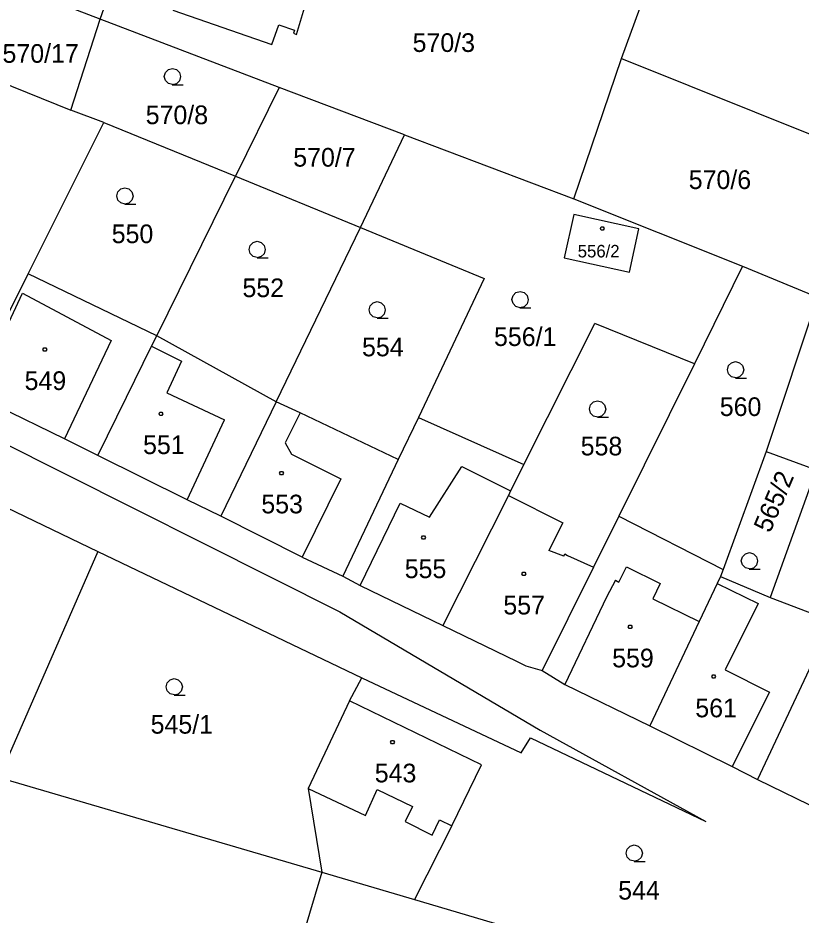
# Model space of a CAD drawing. Extents: x -759060 to -757386, y -1172273 to -1170948.
# Drawn here: x -758258.8 to -758187.4, y -1171734.6 to -1171652.9 of the extents above; entities that cross this region are included whole.
import ezdxf

# ---------------------------------------------------------------- set-up
doc = ezdxf.new("R2010")
doc.units = 0
for name, color, linetype in [('Vrstva 1', 7, 'Continuous'), ('Vrstva 12', 7, 'Continuous'), ('Vrstva 2', 7, 'Continuous'), ('Vrstva 3', 7, 'Continuous'), ('Vrstva 4', 7, 'Continuous'), ('Vrstva 5', 7, 'Continuous')]:
    doc.layers.add(name, color=color, linetype=linetype)

msp = doc.modelspace()

# ---------------------------------------------------------------- linework, layer by layer
at = {"layer": 'Vrstva 1'}
for p, q in [((-758251.29, -1171652.99), (-758245.38, -1171635.86)), ((-758251.29, -1171652.99), (-758258.76, -1171650.13)), ((-758233.41, -1171654.38), (-758232.51, -1171651.34)), ((-758203.79, -1171656.58), (-758202.08, -1171651.93)), ((-758244.67, -1171652.18), (-758235.65, -1171655.29)), ((-758253.97, -1171661.29), (-758251.29, -1171652.99)), ((-758234.98, -1171659.23), (-758251.29, -1171652.99)), ((-758235.65, -1171655.29), (-758235.03, -1171653.5)), ((-758235.03, -1171653.5), (-758233.59, -1171654)), ((-758233.59, -1171654), (-758233.69, -1171654.28)), ((-758233.69, -1171654.28), (-758233.41, -1171654.38)), ((-758208.12, -1171669.37), (-758203.79, -1171656.58)), ((-758203.79, -1171656.58), (-758181.48, -1171665.51)), ((-758261.39, -1171658.31), (-758253.97, -1171661.29)), ((-758234.98, -1171659.23), (-758238.98, -1171667.31)), ((-758223.55, -1171663.54), (-758234.98, -1171659.23)), ((-758250.97, -1171662.41), (-758253.97, -1171661.29)), ((-758257.87, -1171676.2), (-758250.97, -1171662.41)), ((-758250.97, -1171662.41), (-758238.98, -1171667.31)), ((-758227.57, -1171671.98), (-758223.55, -1171663.54)), ((-758223.55, -1171663.54), (-758208.12, -1171669.37)), ((-758246.15, -1171681.85), (-758238.98, -1171667.31)), ((-758238.98, -1171667.31), (-758227.57, -1171671.98)), ((-758208.12, -1171669.37), (-758192.74, -1171675.5)), ((-758208.13, -1171670.8), (-758209, -1171674.75)), ((-758202.2, -1171672.11), (-758208.13, -1171670.8)), ((-758235.27, -1171687.87), (-758227.57, -1171671.98)), ((-758227.57, -1171671.98), (-758216.29, -1171676.63)), ((-758203.06, -1171676.05), (-758202.2, -1171672.11)), ((-758209, -1171674.75), (-758203.06, -1171676.05)), ((-758192.74, -1171675.5), (-758197.13, -1171684.41)), ((-758192.74, -1171675.5), (-758185.93, -1171678.31)), ((-758263.26, -1171686.98), (-758257.87, -1171676.2)), ((-758246.15, -1171681.85), (-758257.87, -1171676.2)), ((-758216.29, -1171676.63), (-758222.3, -1171689.28)), ((-758286.85, -1171678.18), (-758229.45, -1171707)), ((-758185.93, -1171678.31), (-758190.6, -1171692.37)), ((-758212.68, -1171693.57), (-758206.2, -1171680.71)), ((-758197.13, -1171684.41), (-758206.2, -1171680.71)), ((-758246.61, -1171682.79), (-758246.15, -1171681.85)), ((-758235.27, -1171687.87), (-758246.15, -1171681.85)), ((-758248.89, -1171687.43), (-758246.61, -1171682.79)), ((-758197.13, -1171684.41), (-758204.03, -1171698.27)), ((-758254.55, -1171691.24), (-758262.74, -1171687.24)), ((-758251.51, -1171692.75), (-758248.89, -1171687.43)), ((-758235.27, -1171687.87), (-758240.3, -1171698.27)), ((-758233.07, -1171688.87), (-758235.27, -1171687.87)), ((-758277.01, -1171689.2), (-758251.53, -1171701.5)), ((-758224.13, -1171693.12), (-758233.07, -1171688.87)), ((-758222.3, -1171689.28), (-758224.13, -1171693.12)), ((-758222.3, -1171689.28), (-758212.68, -1171693.57)), ((-758251.51, -1171692.75), (-758254.55, -1171691.24)), ((-758243.36, -1171696.79), (-758251.51, -1171692.75)), ((-758190.6, -1171692.37), (-758194.52, -1171703.12)), ((-758190.6, -1171692.37), (-758186.03, -1171694.05)), ((-758224.13, -1171693.12), (-758229.17, -1171703.73)), ((-758212.68, -1171693.57), (-758213.89, -1171695.98)), ((-758186.03, -1171694.05), (-758190.23, -1171705.69)), ((-758213.89, -1171695.98), (-758214.09, -1171696.38)), ((-758240.3, -1171698.27), (-758243.36, -1171696.79)), ((-758214.09, -1171696.38), (-758215.64, -1171699.47)), ((-758214.09, -1171696.38), (-758209.13, -1171698.88)), ((-758232.9, -1171702.02), (-758240.3, -1171698.27)), ((-758204.03, -1171698.27), (-758206.33, -1171702.91)), ((-758204.03, -1171698.27), (-758194.52, -1171703.12)), ((-758215.64, -1171699.47), (-758220.06, -1171708.25)), ((-758209.13, -1171698.88), (-758210.41, -1171701.41)), ((-758251.53, -1171701.5), (-758260.55, -1171722.08)), ((-758251.53, -1171701.5), (-758227.44, -1171713.01)), ((-758209.04, -1171701.92), (-758210.41, -1171701.41)), ((-758209.04, -1171701.92), (-758208.94, -1171701.72)), ((-758208.94, -1171701.72), (-758208.69, -1171701.87)), ((-758208.69, -1171701.87), (-758206.33, -1171702.91)), ((-758232.9, -1171702.02), (-758229.17, -1171703.73)), ((-758206.33, -1171702.91), (-758211.02, -1171712.33)), ((-758194.52, -1171703.12), (-758194.76, -1171703.77)), ((-758229.17, -1171703.73), (-758227.6, -1171704.6)), ((-758194.76, -1171703.77), (-758195.06, -1171704.4)), ((-758194.76, -1171703.77), (-758190.23, -1171705.69)), ((-758227.6, -1171704.6), (-758220.06, -1171708.25)), ((-758195.06, -1171704.4), (-758196.69, -1171707.86)), ((-758190.23, -1171705.69), (-758184.62, -1171707.83)), ((-758229.45, -1171707), (-758211.2, -1171717.78)), ((-758220.06, -1171708.25), (-758213.35, -1171711.5)), ((-758196.69, -1171707.86), (-758201.21, -1171717.39)), ((-758184.62, -1171707.83), (-758191.39, -1171722.26)), ((-758213.35, -1171711.5), (-758212.49, -1171711.91)), ((-758212.49, -1171711.91), (-758211.02, -1171712.33)), ((-758211.02, -1171712.33), (-758208.95, -1171713.61)), ((-758228.58, -1171715.1), (-758227.44, -1171713.01)), ((-758227.44, -1171713.01), (-758212.94, -1171719.83)), ((-758208.95, -1171713.61), (-758201.21, -1171717.39)), ((-758228.58, -1171715.1), (-758232.34, -1171723.08)), ((-758216.55, -1171720.92), (-758228.58, -1171715.1)), ((-758201.21, -1171717.39), (-758193.7, -1171721.07)), ((-758211.2, -1171717.78), (-758196.08, -1171726.08)), ((-758212.94, -1171719.83), (-758212.08, -1171718.48)), ((-758212.08, -1171718.48), (-758196.08, -1171726.08)), ((-758219.25, -1171726.48), (-758216.55, -1171720.92)), ((-758193.7, -1171721.07), (-758191.39, -1171722.26)), ((-758260.55, -1171722.08), (-758231.11, -1171730.71)), ((-758191.39, -1171722.26), (-758181.67, -1171727.03)), ((-758232.34, -1171723.08), (-758231.11, -1171730.71)), ((-758196.08, -1171726.08), (-758196.08, -1171726.08)), ((-758219.25, -1171726.48), (-758222.66, -1171733.2)), ((-758231.11, -1171730.71), (-758236.26, -1171748.17)), ((-758231.11, -1171730.71), (-758222.66, -1171733.2)), ((-758222.66, -1171733.2), (-758206.53, -1171737.95))]:
    msp.add_line(p, q, dxfattribs=at)
at = {"layer": 'Vrstva 12'}
for p, q in [((-758233.41, -1171654.38), (-758232.51, -1171651.34)), ((-758244.67, -1171652.18), (-758235.65, -1171655.29)), ((-758235.65, -1171655.29), (-758235.03, -1171653.5)), ((-758235.03, -1171653.5), (-758233.59, -1171654)), ((-758233.59, -1171654), (-758233.69, -1171654.28)), ((-758233.69, -1171654.28), (-758233.41, -1171654.38)), ((-758208.13, -1171670.8), (-758209, -1171674.75)), ((-758202.2, -1171672.11), (-758208.13, -1171670.8)), ((-758203.06, -1171676.05), (-758202.2, -1171672.11)), ((-758209, -1171674.75), (-758203.06, -1171676.05)), ((-758262.74, -1171687.24), (-758258.39, -1171677.95)), ((-758258.39, -1171677.95), (-758250.29, -1171682.26)), ((-758250.29, -1171682.26), (-758254.55, -1171691.24)), ((-758248.89, -1171687.43), (-758246.61, -1171682.79)), ((-758246.61, -1171682.79), (-758243.88, -1171684.14)), ((-758243.88, -1171684.14), (-758245.23, -1171687.05)), ((-758245.23, -1171687.05), (-758239.97, -1171689.5)), ((-758254.55, -1171691.24), (-758262.74, -1171687.24)), ((-758251.51, -1171692.75), (-758248.89, -1171687.43)), ((-758235.27, -1171687.87), (-758240.3, -1171698.27)), ((-758233.07, -1171688.87), (-758235.27, -1171687.87)), ((-758243.36, -1171696.79), (-758239.97, -1171689.5)), ((-758233.07, -1171688.87), (-758234.43, -1171691.59)), ((-758234.43, -1171691.59), (-758233.87, -1171692.62)), ((-758243.36, -1171696.79), (-758251.51, -1171692.75)), ((-758233.87, -1171692.62), (-758229.38, -1171694.87)), ((-758221.27, -1171698.38), (-758218.35, -1171693.74)), ((-758218.35, -1171693.74), (-758213.89, -1171695.98)), ((-758229.38, -1171694.87), (-758232.9, -1171702.02)), ((-758213.89, -1171695.98), (-758214.09, -1171696.38)), ((-758214.09, -1171696.38), (-758215.64, -1171699.47)), ((-758214.09, -1171696.38), (-758215.64, -1171699.47)), ((-758214.09, -1171696.38), (-758209.13, -1171698.88)), ((-758227.6, -1171704.6), (-758223.96, -1171697.08)), ((-758223.96, -1171697.08), (-758221.27, -1171698.38)), ((-758232.9, -1171702.02), (-758240.3, -1171698.27)), ((-758215.64, -1171699.47), (-758220.06, -1171708.25)), ((-758215.64, -1171699.47), (-758220.06, -1171708.25)), ((-758209.13, -1171698.88), (-758210.41, -1171701.41)), ((-758209.04, -1171701.92), (-758210.41, -1171701.41)), ((-758209.04, -1171701.92), (-758208.94, -1171701.72)), ((-758208.94, -1171701.72), (-758208.69, -1171701.87)), ((-758208.69, -1171701.87), (-758206.33, -1171702.91)), ((-758206.33, -1171702.91), (-758211.02, -1171712.33)), ((-758204.01, -1171704.28), (-758203.34, -1171702.9)), ((-758203.34, -1171702.9), (-758200.25, -1171704.4)), ((-758204.34, -1171704.12), (-758205.14, -1171705.66)), ((-758204.34, -1171704.12), (-758204.01, -1171704.28)), ((-758227.6, -1171704.6), (-758220.06, -1171708.25)), ((-758200.25, -1171704.4), (-758200.93, -1171705.8)), ((-758195.06, -1171704.4), (-758196.69, -1171707.86)), ((-758195.06, -1171704.4), (-758191.32, -1171706.24)), ((-758205.14, -1171705.66), (-758208.95, -1171713.61)), ((-758200.93, -1171705.8), (-758196.69, -1171707.86)), ((-758191.32, -1171706.24), (-758194.33, -1171712.27)), ((-758220.06, -1171708.25), (-758213.35, -1171711.5)), ((-758196.69, -1171707.86), (-758201.21, -1171717.39)), ((-758196.69, -1171707.86), (-758201.21, -1171717.39)), ((-758213.35, -1171711.5), (-758212.49, -1171711.91)), ((-758212.49, -1171711.91), (-758211.02, -1171712.33)), ((-758194.33, -1171712.27), (-758190.3, -1171714.31)), ((-758208.95, -1171713.61), (-758201.21, -1171717.39)), ((-758190.3, -1171714.31), (-758193.7, -1171721.07)), ((-758228.58, -1171715.1), (-758232.34, -1171723.08)), ((-758216.55, -1171720.92), (-758228.58, -1171715.1)), ((-758201.21, -1171717.39), (-758193.7, -1171721.07)), ((-758219.25, -1171726.48), (-758216.55, -1171720.92)), ((-758232.34, -1171723.08), (-758227.11, -1171725.54)), ((-758227.11, -1171725.54), (-758226.04, -1171723.18)), ((-758226.04, -1171723.18), (-758222.84, -1171724.74)), ((-758222.84, -1171724.74), (-758223.49, -1171726.09)), ((-758223.49, -1171726.09), (-758221.03, -1171727.33)), ((-758221.03, -1171727.33), (-758220.36, -1171725.94)), ((-758220.36, -1171725.94), (-758219.25, -1171726.48))]:
    msp.add_line(p, q, dxfattribs=at)
at = {"layer": 'Vrstva 3'}
for points in [[(-758244.71, -1171658.96), (-758245.09, -1171658.86), (-758245.36, -1171658.59), (-758245.46, -1171658.22), (-758245.36, -1171657.85), (-758245.09, -1171657.58), (-758244.72, -1171657.48), (-758244.35, -1171657.58), (-758244.08, -1171657.85), (-758243.98, -1171658.23), (-758244.08, -1171658.61), (-758244.35, -1171658.88), (-758244.73, -1171658.98), (-758243.73, -1171658.98)], [(-758249.04, -1171669.84), (-758249.42, -1171669.74), (-758249.69, -1171669.47), (-758249.79, -1171669.1), (-758249.69, -1171668.73), (-758249.42, -1171668.46), (-758249.05, -1171668.36), (-758248.68, -1171668.46), (-758248.41, -1171668.73), (-758248.31, -1171669.11), (-758248.41, -1171669.49), (-758248.68, -1171669.76), (-758249.06, -1171669.86), (-758248.06, -1171669.86)], [(-758236.98, -1171674.71), (-758237.36, -1171674.61), (-758237.63, -1171674.34), (-758237.73, -1171673.97), (-758237.63, -1171673.6), (-758237.36, -1171673.33), (-758236.99, -1171673.23), (-758236.62, -1171673.33), (-758236.35, -1171673.6), (-758236.25, -1171673.98), (-758236.35, -1171674.36), (-758236.62, -1171674.63), (-758237, -1171674.73), (-758236, -1171674.73)], [(-758213.02, -1171679.28), (-758213.4, -1171679.18), (-758213.67, -1171678.91), (-758213.77, -1171678.54), (-758213.67, -1171678.17), (-758213.4, -1171677.9), (-758213.03, -1171677.8), (-758212.66, -1171677.9), (-758212.39, -1171678.17), (-758212.29, -1171678.55), (-758212.39, -1171678.93), (-758212.66, -1171679.2), (-758213.04, -1171679.3), (-758212.04, -1171679.3)], [(-758226.04, -1171680.21), (-758226.42, -1171680.11), (-758226.69, -1171679.84), (-758226.79, -1171679.47), (-758226.69, -1171679.1), (-758226.42, -1171678.83), (-758226.05, -1171678.73), (-758225.68, -1171678.83), (-758225.41, -1171679.1), (-758225.31, -1171679.48), (-758225.41, -1171679.86), (-758225.68, -1171680.13), (-758226.06, -1171680.23), (-758225.06, -1171680.23)], [(-758193.37, -1171685.67), (-758193.75, -1171685.57), (-758194.02, -1171685.3), (-758194.12, -1171684.93), (-758194.02, -1171684.56), (-758193.75, -1171684.29), (-758193.38, -1171684.19), (-758193.01, -1171684.29), (-758192.74, -1171684.56), (-758192.64, -1171684.94), (-758192.74, -1171685.32), (-758193.01, -1171685.59), (-758193.39, -1171685.69), (-758192.39, -1171685.69)], [(-758205.95, -1171689.25), (-758206.33, -1171689.15), (-758206.6, -1171688.88), (-758206.7, -1171688.51), (-758206.6, -1171688.14), (-758206.33, -1171687.87), (-758205.96, -1171687.77), (-758205.59, -1171687.87), (-758205.32, -1171688.14), (-758205.22, -1171688.52), (-758205.32, -1171688.9), (-758205.59, -1171689.17), (-758205.97, -1171689.27), (-758204.97, -1171689.27)], [(-758192.11, -1171703.08), (-758192.49, -1171702.98), (-758192.76, -1171702.71), (-758192.86, -1171702.34), (-758192.76, -1171701.97), (-758192.49, -1171701.7), (-758192.12, -1171701.6), (-758191.75, -1171701.7), (-758191.48, -1171701.97), (-758191.38, -1171702.35), (-758191.48, -1171702.73), (-758191.75, -1171703), (-758192.13, -1171703.1), (-758191.13, -1171703.1)], [(-758244.54, -1171714.56), (-758244.92, -1171714.46), (-758245.19, -1171714.19), (-758245.29, -1171713.82), (-758245.19, -1171713.45), (-758244.92, -1171713.18), (-758244.55, -1171713.08), (-758244.18, -1171713.18), (-758243.91, -1171713.45), (-758243.81, -1171713.83), (-758243.91, -1171714.21), (-758244.18, -1171714.48), (-758244.56, -1171714.58), (-758243.56, -1171714.58)], [(-758202.61, -1171729.71), (-758202.99, -1171729.61), (-758203.26, -1171729.34), (-758203.36, -1171728.97), (-758203.26, -1171728.6), (-758202.99, -1171728.33), (-758202.62, -1171728.23), (-758202.25, -1171728.33), (-758201.98, -1171728.6), (-758201.88, -1171728.98), (-758201.98, -1171729.36), (-758202.25, -1171729.63), (-758202.63, -1171729.73), (-758201.63, -1171729.73)]]:
    msp.add_lwpolyline(points, dxfattribs=at)
at = {"layer": 'Vrstva 4'}
for p, q in [((-758262.74, -1171687.24), (-758258.39, -1171677.95)), ((-758258.39, -1171677.95), (-758250.29, -1171682.26)), ((-758250.29, -1171682.26), (-758254.55, -1171691.24)), ((-758246.61, -1171682.79), (-758243.88, -1171684.14)), ((-758243.88, -1171684.14), (-758245.23, -1171687.05)), ((-758245.23, -1171687.05), (-758239.97, -1171689.5)), ((-758243.36, -1171696.79), (-758239.97, -1171689.5)), ((-758233.07, -1171688.87), (-758234.43, -1171691.59)), ((-758234.43, -1171691.59), (-758233.87, -1171692.62)), ((-758233.87, -1171692.62), (-758229.38, -1171694.87)), ((-758221.27, -1171698.38), (-758218.35, -1171693.74)), ((-758218.35, -1171693.74), (-758213.89, -1171695.98)), ((-758229.38, -1171694.87), (-758232.9, -1171702.02)), ((-758227.6, -1171704.6), (-758223.96, -1171697.08)), ((-758223.96, -1171697.08), (-758221.27, -1171698.38)), ((-758204.01, -1171704.28), (-758203.34, -1171702.9)), ((-758203.34, -1171702.9), (-758200.25, -1171704.4)), ((-758204.34, -1171704.12), (-758205.14, -1171705.66)), ((-758204.34, -1171704.12), (-758204.01, -1171704.28)), ((-758200.25, -1171704.4), (-758200.93, -1171705.8)), ((-758195.06, -1171704.4), (-758191.32, -1171706.24)), ((-758205.14, -1171705.66), (-758208.95, -1171713.61)), ((-758200.93, -1171705.8), (-758196.69, -1171707.86)), ((-758191.32, -1171706.24), (-758194.33, -1171712.27)), ((-758194.33, -1171712.27), (-758190.3, -1171714.31)), ((-758190.3, -1171714.31), (-758193.7, -1171721.07)), ((-758232.34, -1171723.08), (-758227.11, -1171725.54)), ((-758227.11, -1171725.54), (-758226.04, -1171723.18)), ((-758226.04, -1171723.18), (-758222.84, -1171724.74)), ((-758222.84, -1171724.74), (-758223.49, -1171726.09)), ((-758223.49, -1171726.09), (-758221.03, -1171727.33)), ((-758221.03, -1171727.33), (-758220.36, -1171725.94)), ((-758220.36, -1171725.94), (-758219.25, -1171726.48))]:
    msp.add_line(p, q, dxfattribs=at)
at = {"layer": 'Vrstva 5'}
for points in [[(-758205.44, -1171671.91), (-758205.35, -1171672.06), (-758205.44, -1171672.21), (-758205.62, -1171672.21), (-758205.71, -1171672.06), (-758205.62, -1171671.91)], [(-758256.26, -1171682.93), (-758256.17, -1171683.08), (-758256.26, -1171683.23), (-758256.44, -1171683.23), (-758256.53, -1171683.08), (-758256.44, -1171682.93)], [(-758245.67, -1171688.8), (-758245.58, -1171688.95), (-758245.67, -1171689.1), (-758245.85, -1171689.1), (-758245.94, -1171688.95), (-758245.85, -1171688.8)], [(-758234.69, -1171694.2), (-758234.6, -1171694.35), (-758234.69, -1171694.5), (-758234.87, -1171694.5), (-758234.96, -1171694.35), (-758234.87, -1171694.2)], [(-758221.73, -1171700.07), (-758221.64, -1171700.22), (-758221.73, -1171700.37), (-758221.91, -1171700.37), (-758222, -1171700.22), (-758221.91, -1171700.07)], [(-758212.59, -1171703.38), (-758212.5, -1171703.53), (-758212.59, -1171703.68), (-758212.77, -1171703.68), (-758212.86, -1171703.53), (-758212.77, -1171703.38)], [(-758202.9, -1171708.21), (-758202.81, -1171708.36), (-758202.9, -1171708.51), (-758203.08, -1171708.51), (-758203.17, -1171708.36), (-758203.08, -1171708.21)], [(-758195.29, -1171712.74), (-758195.2, -1171712.89), (-758195.29, -1171713.04), (-758195.47, -1171713.04), (-758195.56, -1171712.89), (-758195.47, -1171712.74)], [(-758224.57, -1171718.71), (-758224.48, -1171718.86), (-758224.57, -1171719.01), (-758224.75, -1171719.01), (-758224.84, -1171718.86), (-758224.75, -1171718.71)]]:
    msp.add_lwpolyline(points, close=True, dxfattribs=at)

# ---------------------------------------------------------------- texts
at = {"layer": 'Vrstva 2'}
for s, height, p in [('570/3', 1.7, (-758222.823, -1171655.98)), ('570/17', 1.7, (-758260.208, -1171656.97)), ('570/8', 1.7, (-758247.153, -1171662.56)), ('570/7', 1.7, (-758233.703, -1171666.43)), ('570/6', 1.7, (-758197.653, -1171668.47)), ('550', 1.7, (-758250.253, -1171673.4)), ('556/2', 1.14, (-758207.771, -1171674.7)), ('552', 1.7, (-758238.333, -1171678.32)), ('556/1', 1.7, (-758215.403, -1171682.77)), ('554', 1.7, (-758227.433, -1171683.71)), ('549', 1.7, (-758258.193, -1171686.78)), ('560', 1.7, (-758194.823, -1171689.15)), ('551', 1.7, (-758247.393, -1171692.62)), ('558', 1.7, (-758207.503, -1171692.74)), ('553', 1.7, (-758236.613, -1171698.02)), ('555', 1.7, (-758223.543, -1171703.92)), ('557', 1.7, (-758214.553, -1171707.23)), ('559', 1.7, (-758204.633, -1171712.05)), ('561', 1.7, (-758197.053, -1171716.6)), ('545/1', 1.7, (-758246.703, -1171718.09)), ('543', 1.7, (-758226.273, -1171722.53)), ('544', 1.7, (-758204.083, -1171733.21))]:
    msp.add_text(s, height=height, dxfattribs=at).set_placement(p)
msp.add_text('565/2', height=1.7, rotation=67.03606, dxfattribs=at).set_placement((-758190.237, -1171699.881))

doc.saveas('drawing.dxf')
